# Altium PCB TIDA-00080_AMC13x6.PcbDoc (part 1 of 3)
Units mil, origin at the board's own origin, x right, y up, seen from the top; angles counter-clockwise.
Board outline 7283.46 x 2559.06 mil, 4 copper layers (Top Layer, MidLayer1, MidLayer2, Bottom Layer), stack 61.2 mil thick; 372 components, 160 nets, 901 pads, 256 vias.
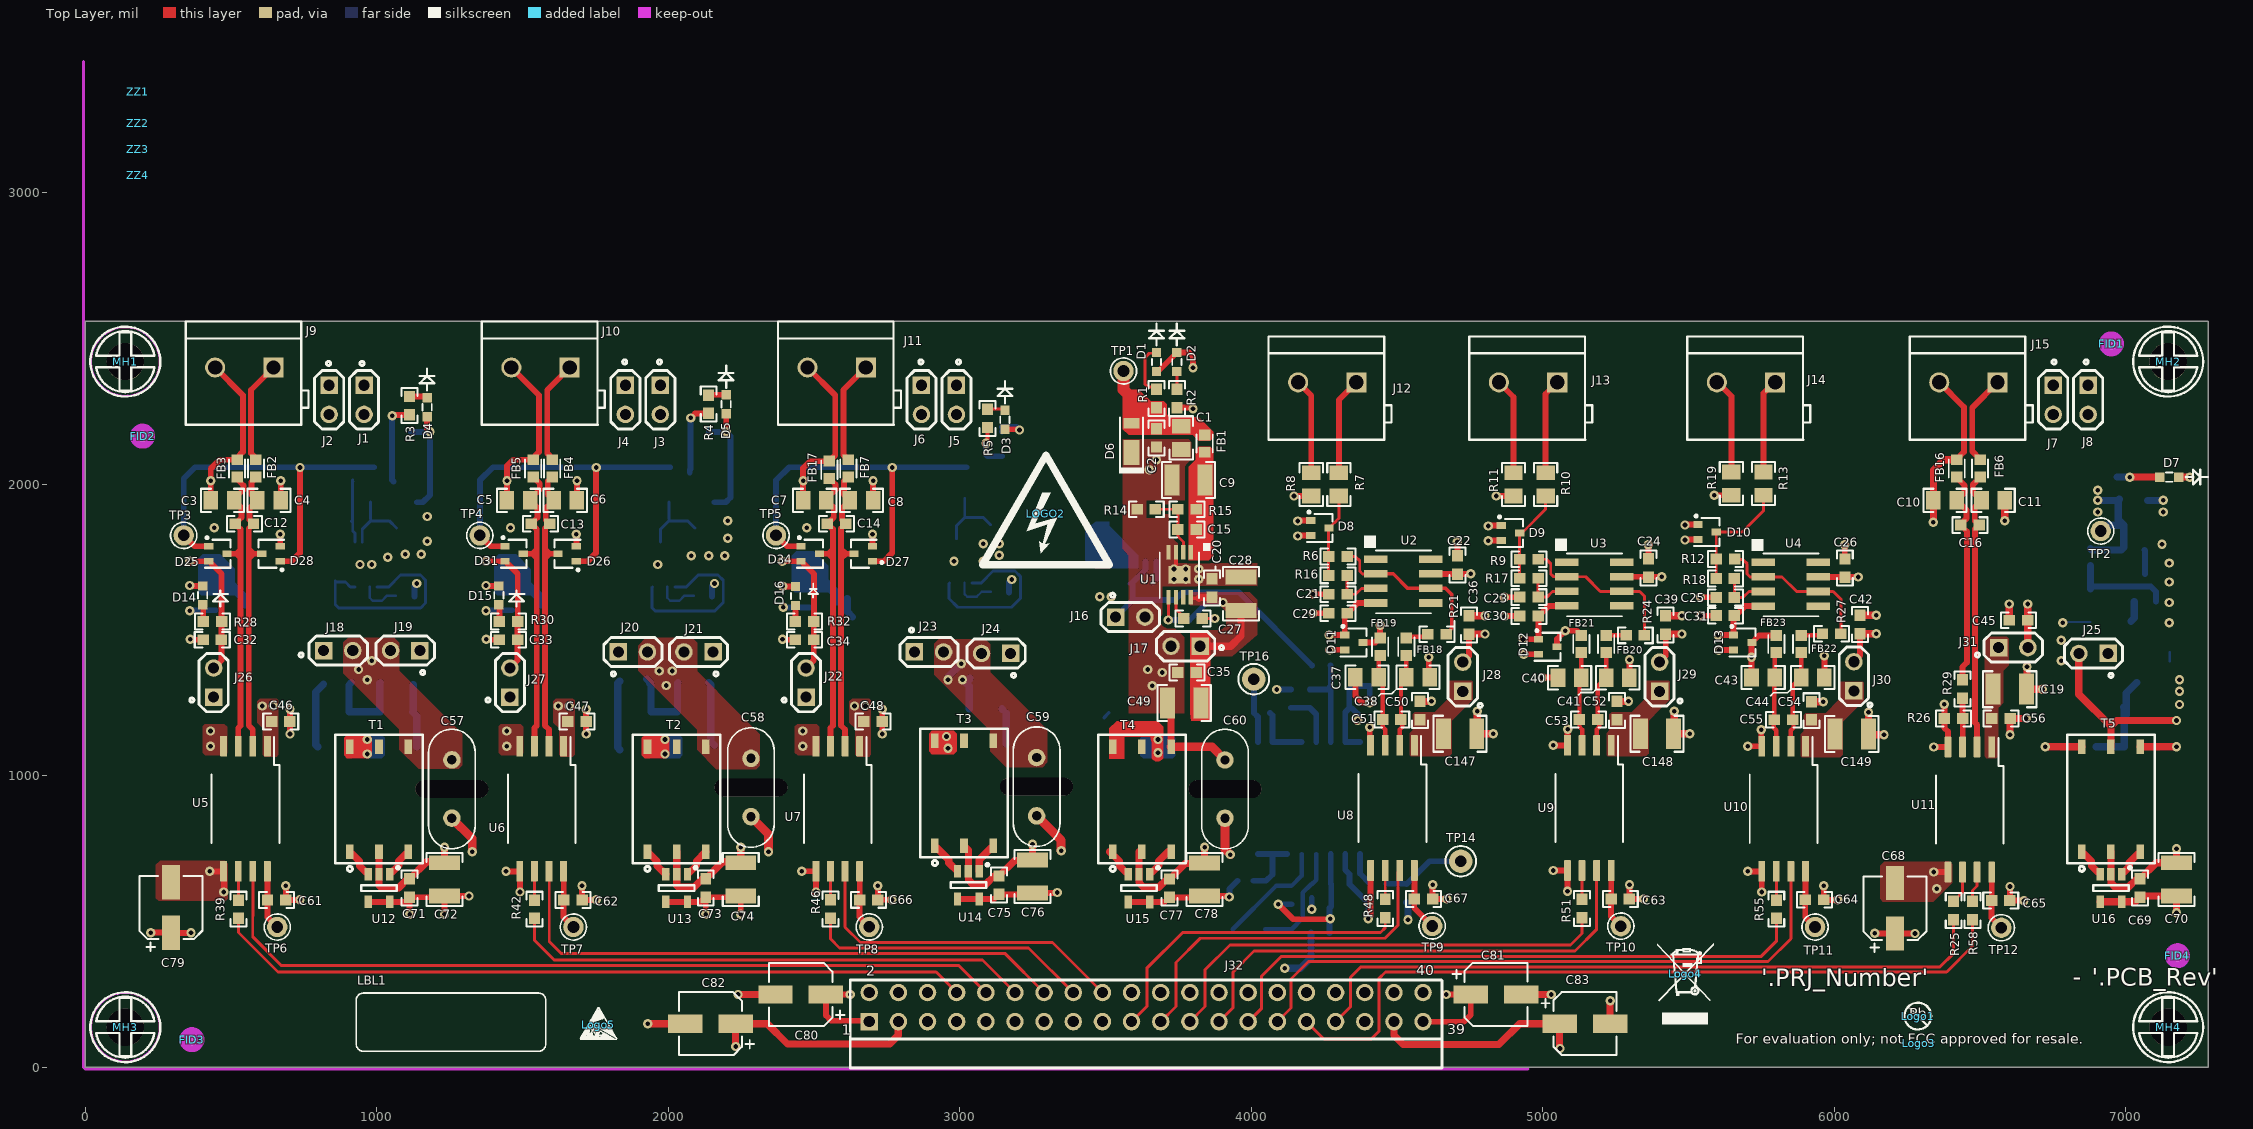
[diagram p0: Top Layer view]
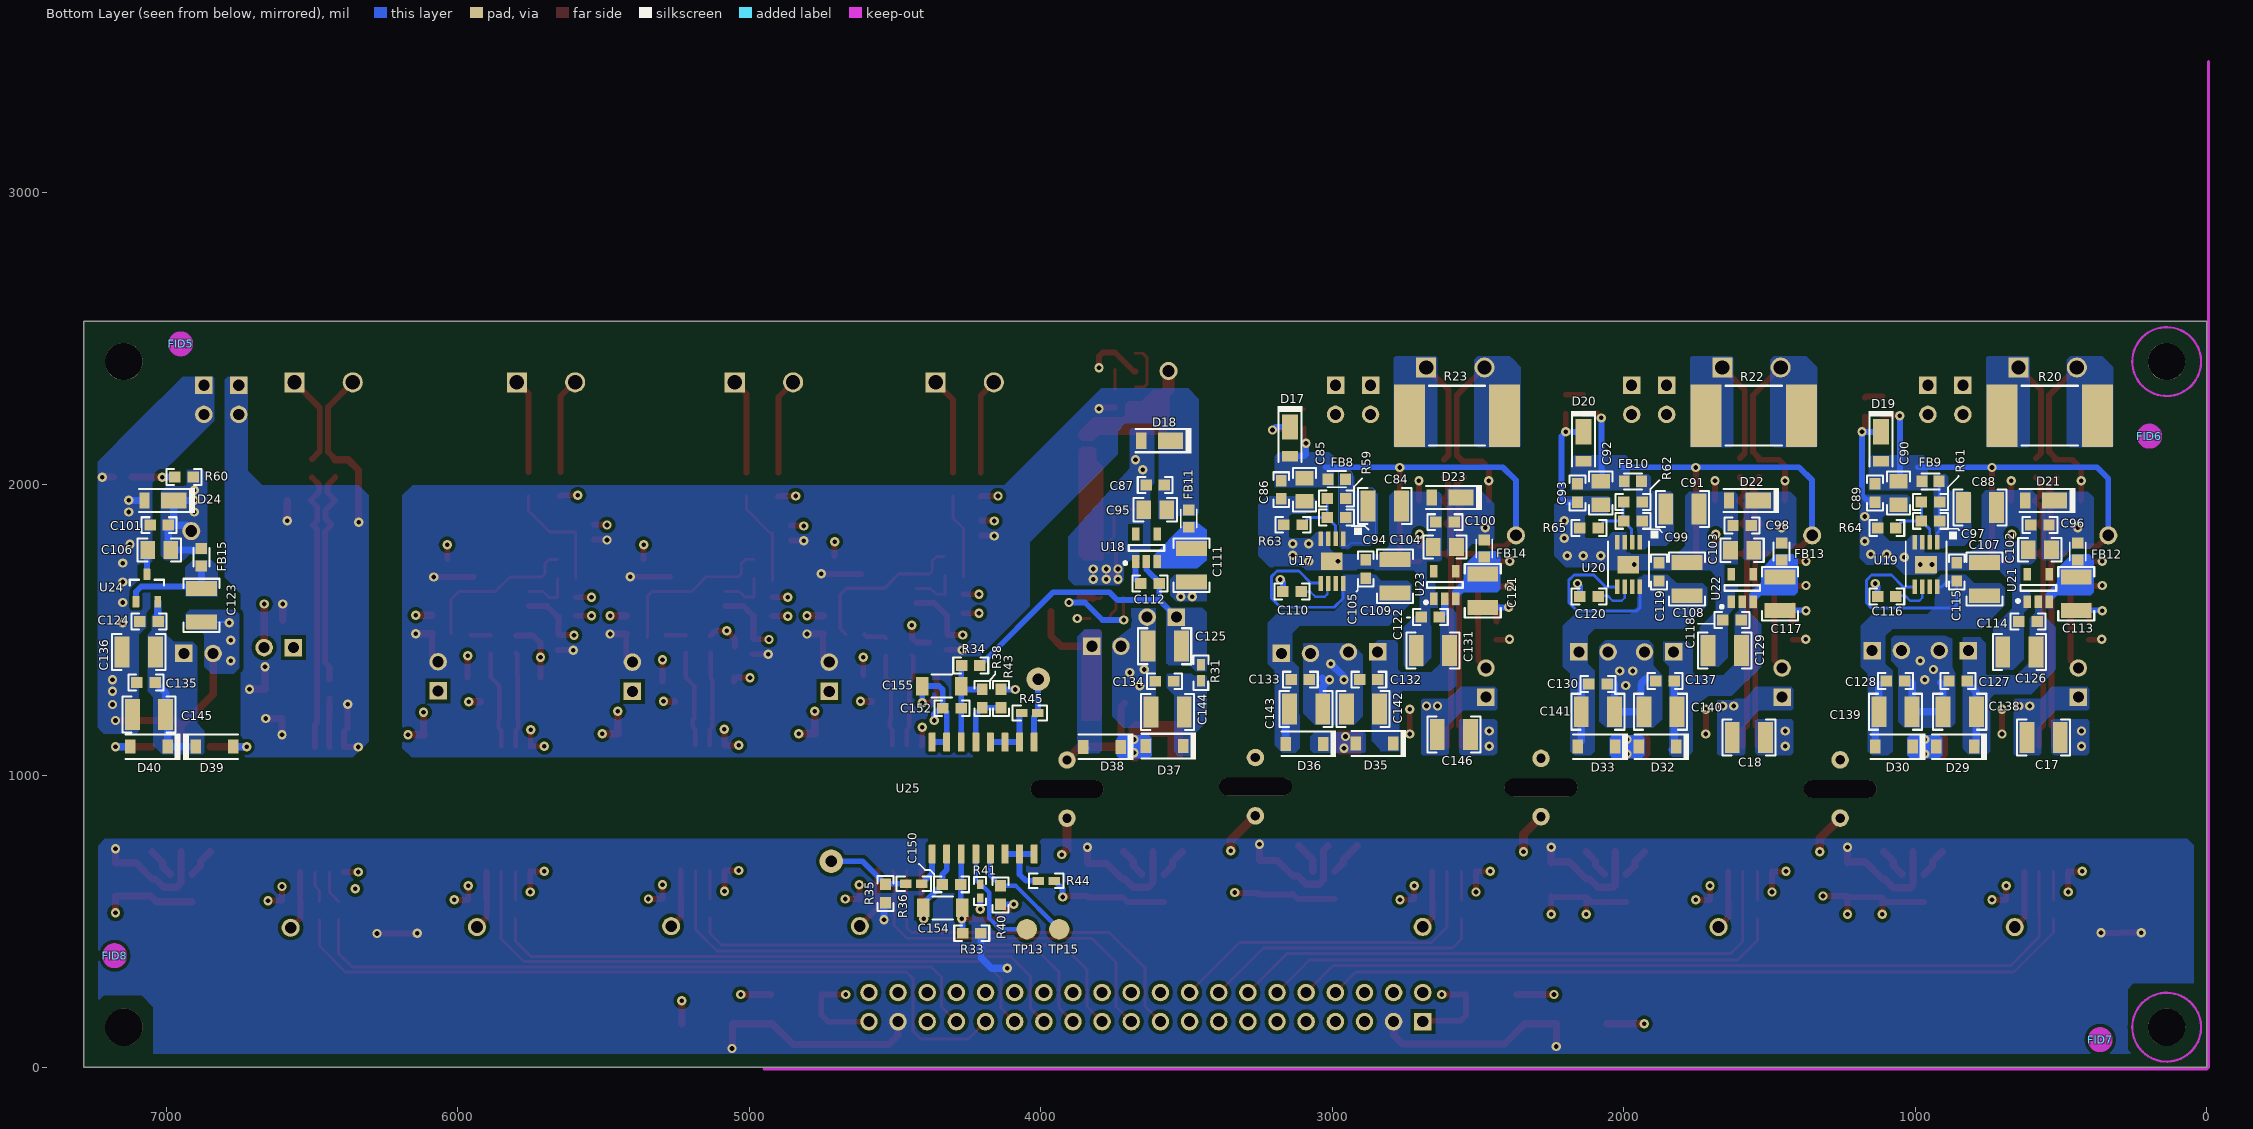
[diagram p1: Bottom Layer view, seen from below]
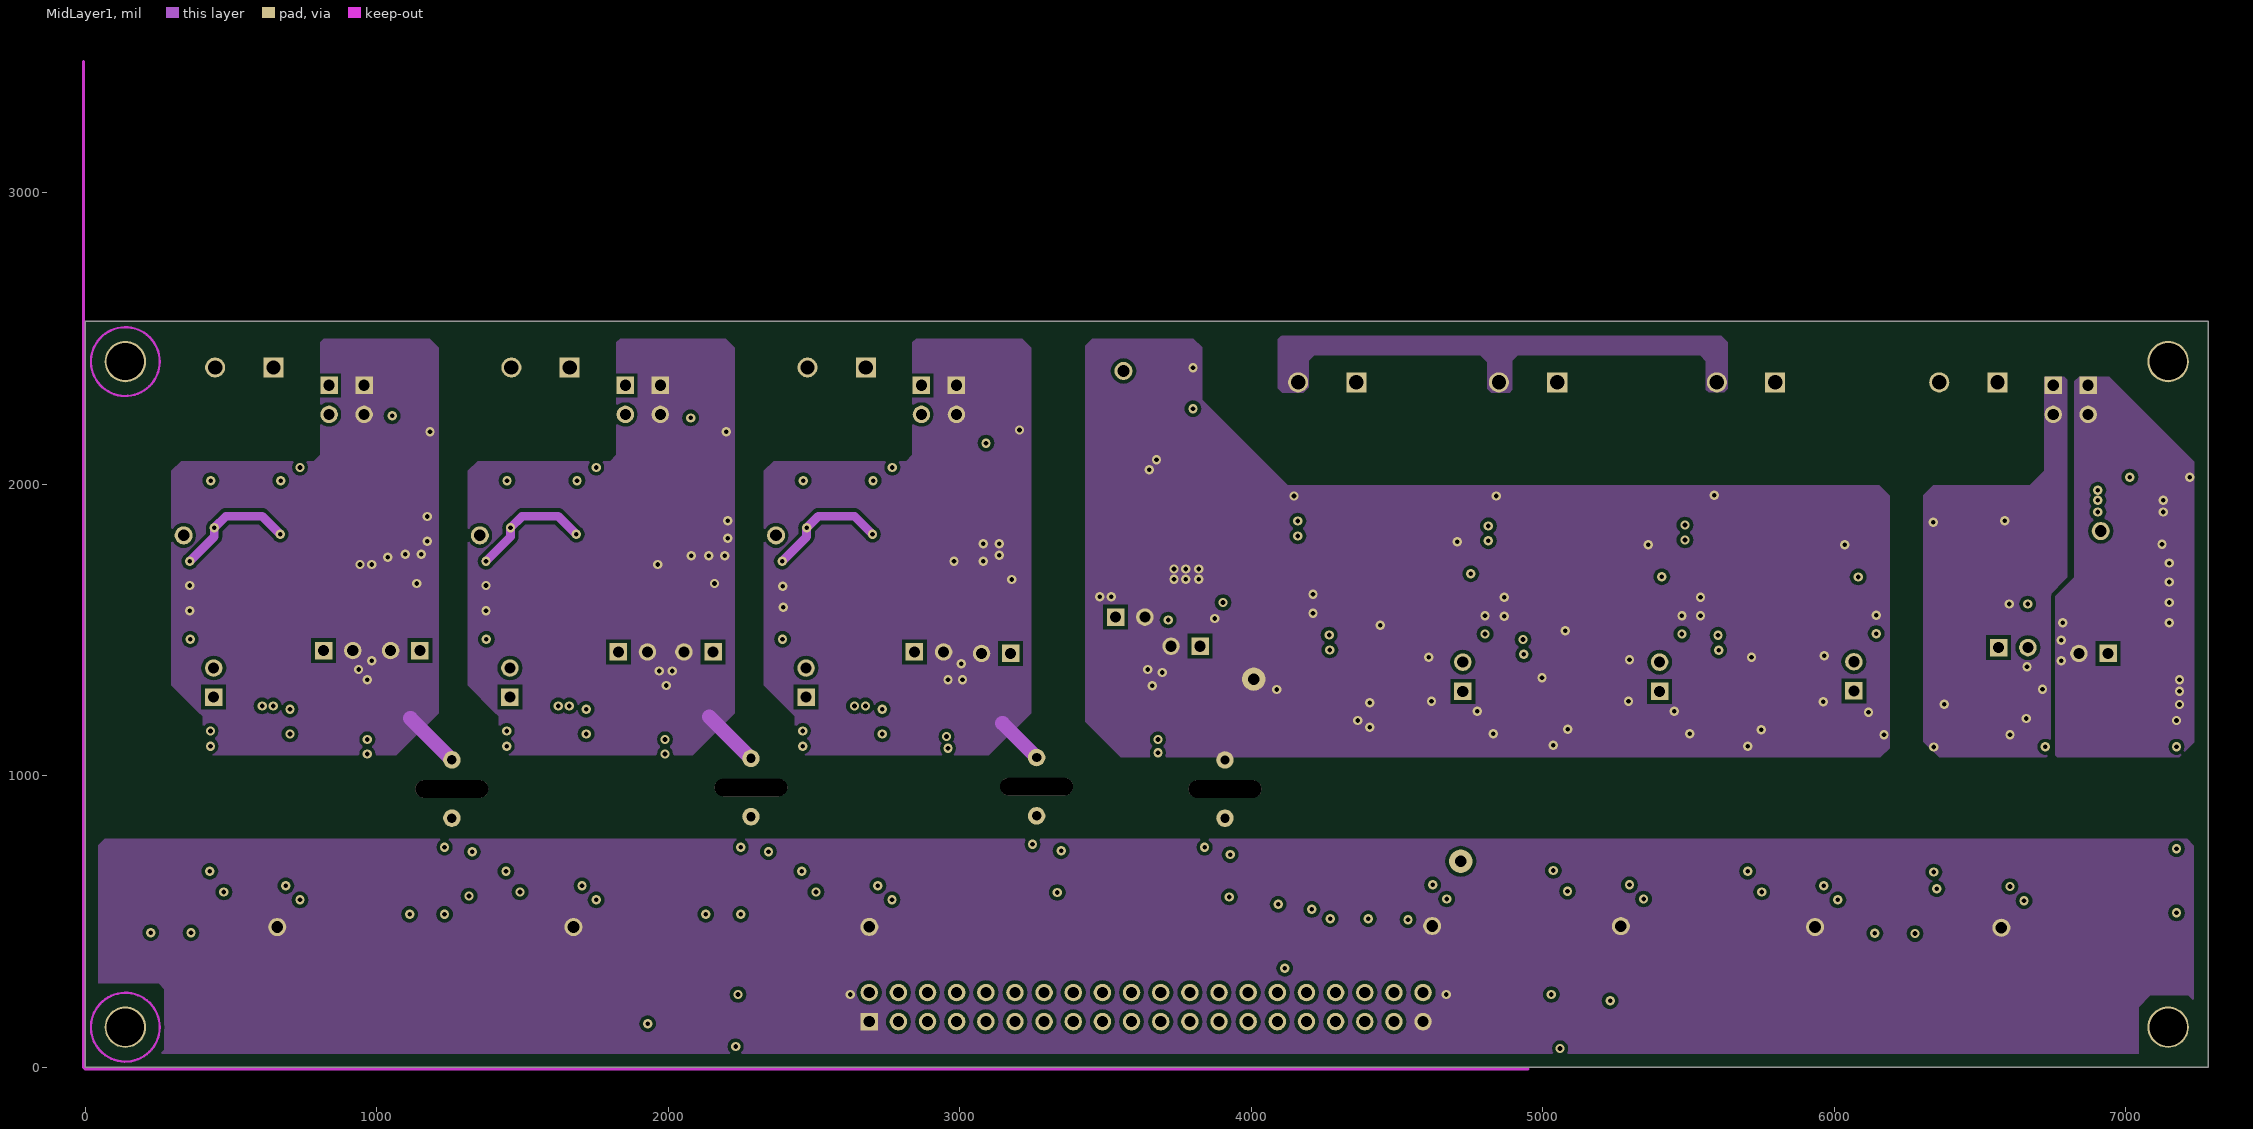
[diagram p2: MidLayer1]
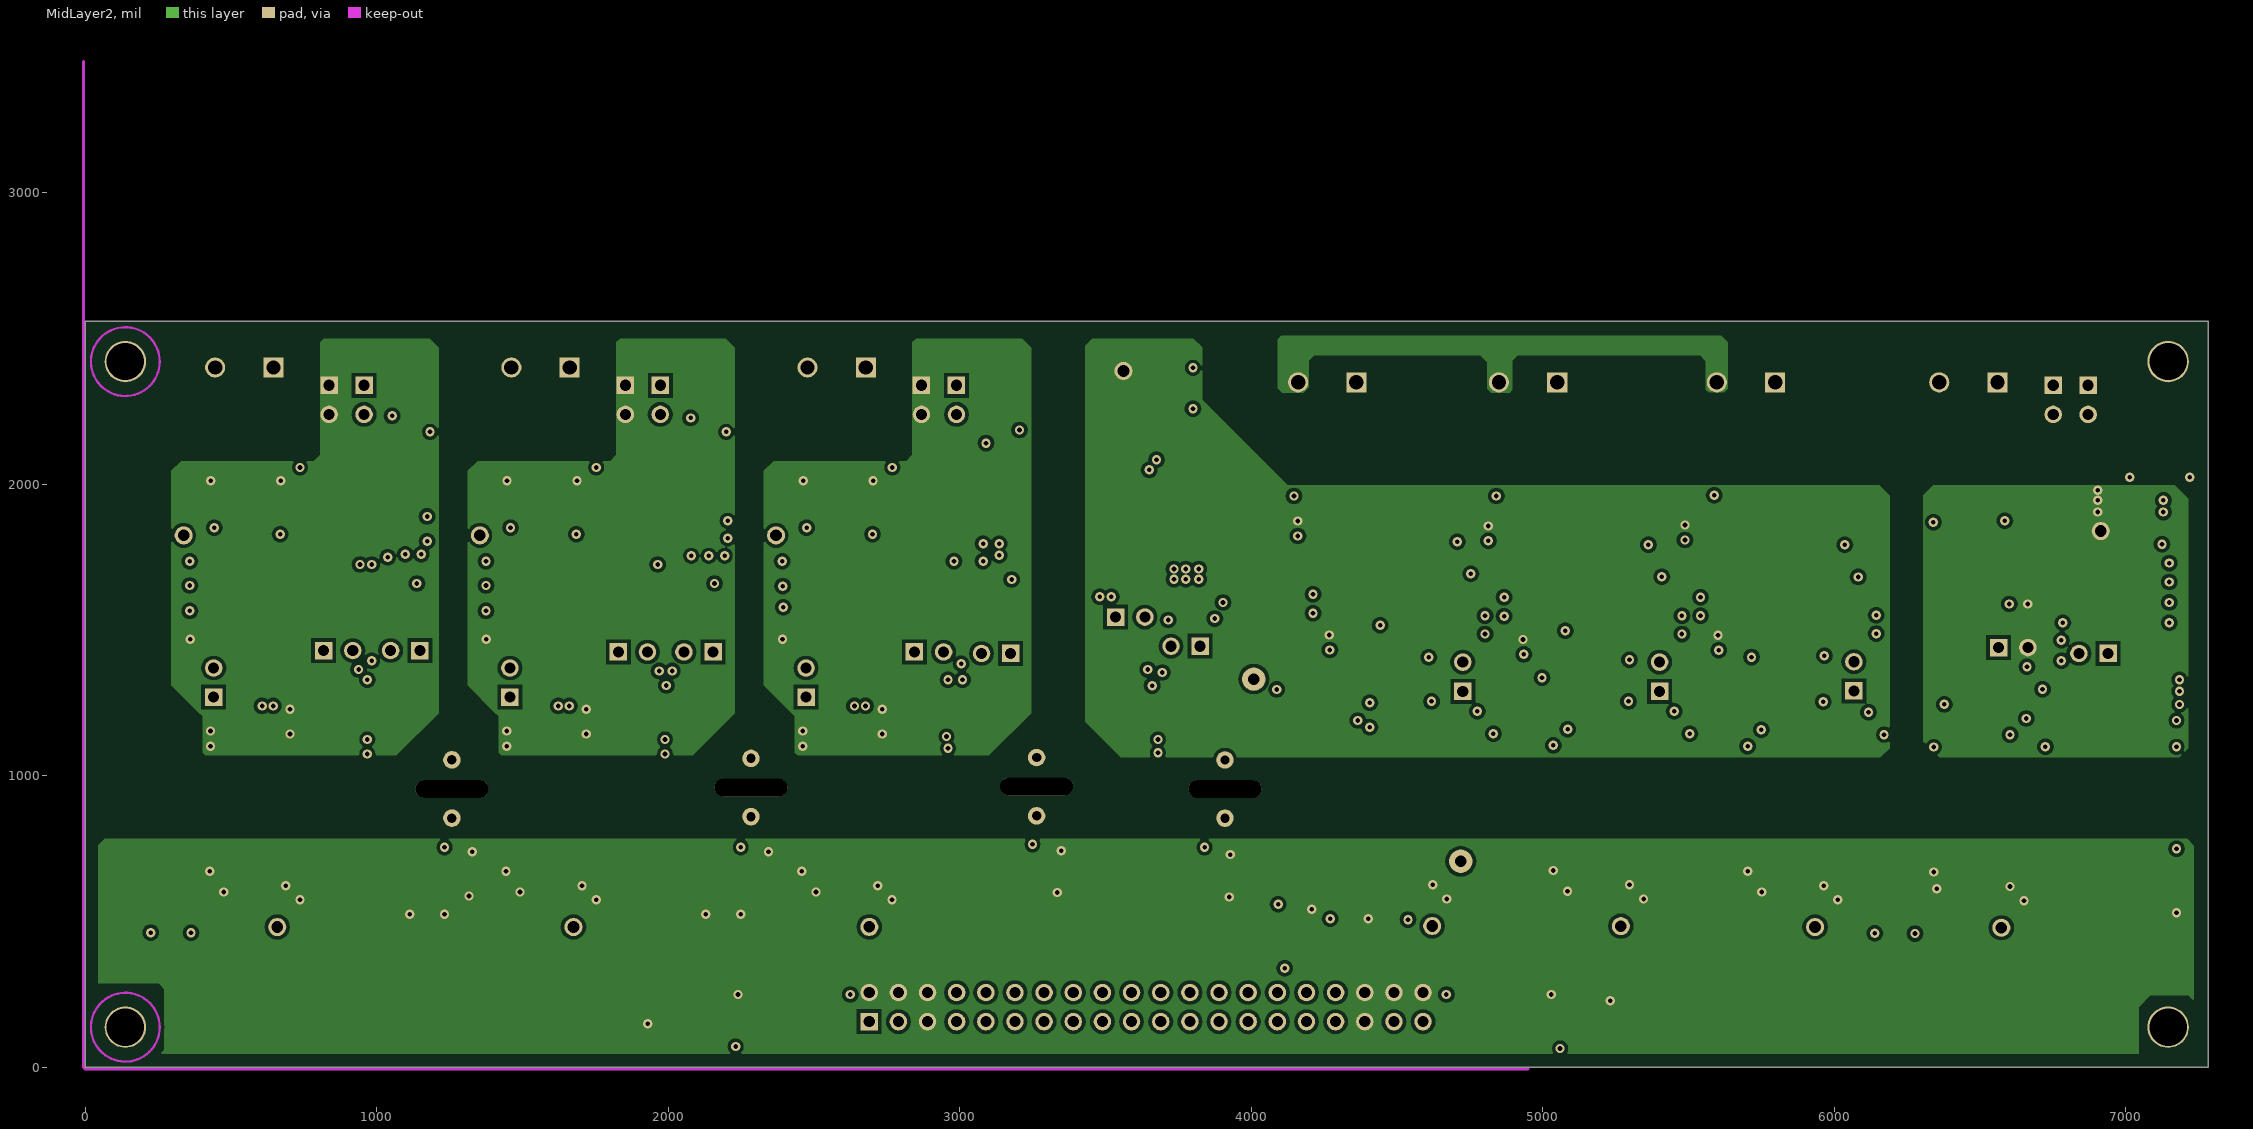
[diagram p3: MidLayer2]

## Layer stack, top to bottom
Top Solder: solder mask 0.4, Solder Resist, Dk 3.5
Top Layer: signal copper 2.8
Dielectric1: core 16.6, FR-4, Dk 4.8
MidLayer1: signal copper 2.8
Dielectric2: prepreg 16.8, FR-4, Dk 4.8
MidLayer2: signal copper 2.8
Dielectric3: core 16.6, FR-4, Dk 4.8
Bottom Layer: signal copper 2.8
Bottom Solder: solder mask 0.4, Solder Resist, Dk 3.5

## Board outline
0,0 7283.46,0 7283.46,2559.06 0,2559.06

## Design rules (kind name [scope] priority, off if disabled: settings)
AcuteAngle [All] p1 off: minimum=4.50000000000000E+0001 checktracksonly=FALSE
AssemblyTestPointUsage [All] p1 off: valid=2
AssemblyTestpoint [All] p1 off: testpointundercomponent=TRUE minsize=40 maxsize=100 preferedsize=60 minholesize=0 maxholesize=40 preferedholesize=32 testpointgrid=1 usegrid=TRUE gridtolerance=0.01 allowsidetop=TRUE allowsidebottom=TRUE
Clearance Clearance_POLY_POLY [InPoly vs InPoly] p1: gap=15 ignorepadtopadclearanceinfootprint=FALSE except(0: Arc-Hole Track-Hole SMDPad-Hole THPad-Hole Via-Hole Fill-Hole Poly-Hole Region-Hole Text-Hole)
Clearance Clearance_Poly [InPolygon] p2: gap=12 ignorepadtopadclearanceinfootprint=FALSE except(0: Arc-Hole Track-Hole SMDPad-Hole THPad-Hole Via-Hole Fill-Hole Poly-Hole Region-Hole Text-Hole)
Clearance [All] p3: gap=8 ignorepadtopadclearanceinfootprint=FALSE except(0: Arc-Hole Track-Hole SMDPad-Hole THPad-Hole Via-Hole Fill-Hole Poly-Hole Region-Hole Text-Hole)
ComponentClearance ComponentClearance_Logo [InComponentClass('Logo')] p1 off: gap=50 collisioncheckmode=3 verticalgap=10 showdistances=FALSE
ComponentClearance ComponentClearance_ScrewToNut [(HasFootprint('NY PMS 440 0025 PH')) vs (HasFootprint('Keystone_1902C'))] p2 off: gap=5 collisioncheckmode=3 verticalgap=10 showdistances=FALSE
ComponentClearance ComponentClearance_MountingHoles [InComponentClass('Mounting Holes')] p3 off: gap=250 collisioncheckmode=3 verticalgap=100000 showdistances=FALSE
ComponentClearance ComponentClearance_SmallPassives [HasFootprint('0201*') or HasFootprint('0402*') or HasFootprint('0508') or HasFootprint('0603*') or HasFootprint('0612') or HasFootprint('0805*') or HasFootprint('0815*') or HasFootprint('0830*') or HasFootprint('1206*') or HasFootprint('1210*') or HasFootprint('1808*') or HasFootprint('1812*') or HasFootprint('1825*') or HasFootprint('2010*') or HasFootprint('2220*') or HasFootprint('2225*') or HasFootprint('2512*') or HasFootprint('2728*') or HasFootprint('3518*') vs HasFootprint('0201*') or HasFootprint('0402*') or HasFootprint('0508') or HasFootprint('0603*') or HasFootprint('0612') or HasFootprint('0805*') or HasFootprint('0815*') or HasFootprint('0830*') or HasFootprint('1206*') or HasFootprint('1210*') or HasFootprint('1808*') or HasFootprint('1812*') or HasFootprint('1825*') or HasFootprint('2010*') or HasFootprint('2220*') or HasFootprint('2225*') or HasFootprint('2512*') or HasFootprint('2728*') or HasFootprint('3518*')] p4 off: gap=20 collisioncheckmode=3 verticalgap=10 showdistances=FALSE
ComponentClearance ComponentClearance_THtoSMT [IsThruComponent vs IsSMTComponent] p5 off: gap=100 collisioncheckmode=3 verticalgap=30 showdistances=FALSE
ComponentClearance ComponentClearance_THtoTH [IsThruComponent vs IsThruComponent] p6 off: gap=118.11 collisioncheckmode=3 verticalgap=30 showdistances=FALSE
ComponentClearance [All] p7 off: gap=40 collisioncheckmode=3 verticalgap=10 showdistances=FALSE
DiffPairsRouting DiffPair_RS232DiffPairsRouting [InDifferentialPair ('RS232')] p1: maxlimit=8 minlimit=8 mostfreqgap=8 toplayer_minwidth=15 toplayer_maxwidth=15 toplayer_prefwidth=15 midlayer1_minwidth=15 midlayer1_maxwidth=15 midlayer1_prefwidth=15 midlayer2_minwidth=15 midlayer2_maxwidth=15 midlayer2_prefwidth=15 bottomlayer_minwidth=15 bottomlayer_maxwidth=15 bottomlayer_prefwidth=15 maxuncoupledlength=500
DiffPairsRouting [All] p2: maxlimit=100 minlimit=10 mostfreqgap=10 toplayer_minwidth=15 toplayer_maxwidth=15 toplayer_prefwidth=15 midlayer1_minwidth=15 midlayer1_maxwidth=15 midlayer1_prefwidth=15 midlayer2_minwidth=15 midlayer2_maxwidth=15 midlayer2_prefwidth=15 bottomlayer_minwidth=15 bottomlayer_maxwidth=15 bottomlayer_prefwidth=15 maxuncoupledlength=1000
FabricationTestPointUsage TestPointUsage [All] p1 off: valid=2 allowmultiple=FALSE
FabricationTestpoint Testpoint [All] p1 off: side=3 testpointundercomponent=TRUE minsize=40 maxsize=100 preferedsize=60 minholesize=0 maxholesize=40 preferedholesize=32 testpointgrid=1 allowsidetop=TRUE allowsidebottom=TRUE usegrid=TRUE gridtolerance=0.01
FanoutControl Fanout_LCC [IsLCC] p1 off: bgadir=Out bgaviamode=Centered fanoutstyle=Auto fanoutdirection=Alternating viagrid=1 // Fanout_LCC (Default Rule)
FanoutControl Fanout_BGA [IsBGA] p2 off: bgadir=Out bgaviamode=Centered fanoutstyle=Auto fanoutdirection=Alternating viagrid=1 // Fanout_BGA (Default Rule)
FanoutControl Fanout_SOIC [IsSOIC] p3 off: bgadir=Out bgaviamode=Centered fanoutstyle=Auto fanoutdirection=Alternating viagrid=1 // Fanout_SOIC (Default Rule)
FanoutControl Fanout_Default [All] p4 off: bgadir=Out bgaviamode=Centered fanoutstyle=Auto fanoutdirection=Alternating viagrid=1 // Fanout_Default (Default Rule)
FanoutControl Fanout_Small [(CompPinCount < 5)] p5 off: bgadir=Out bgaviamode=Centered fanoutstyle=Auto fanoutdirection=OutThenIn viagrid=1 // Fanout_Small (Default Rule)
Height [All] p1 off: minheight=0 maxheight=1000 prefheight=500
HoleSize [All] p1 off: absolutevalues=TRUE maxlimit=251 minlimit=8 maxpercent=80.000 minpercent=20.000
HoleToHoleClearance [All] p1 off: gap=10 allowstackedmicrovias=TRUE
LayerPairs [All] p1 off: enforce=TRUE
MatchedLengths DiffPair_RS232MatchedLengths [InDifferentialPair ('RS232')] p1: tolerance=1000 checknetsindiffpair=TRUE checkdiffpairvsdiffpair=FALSE checkxsignals=FALSE checkothers=FALSE
MinimumAnnularRing MinimumAnnularRing_ThermalPadVias [IsVia and InAnyComponent] p1 off: minimumring=5.91
MinimumAnnularRing [All] p2 off: minimumring=8
MinimumSolderMaskSliver MinimumSolderMaskSliver_Logo [InComponentClass('Logo') vs InComponentClass('Logo')] p1 off: minsoldermaskwidth=0.7
MinimumSolderMaskSliver [All] p2 off: minsoldermaskwidth=3.94
NetAntennae [All] p1 off: netantennaetolerance=0
PasteMaskExpansion [All] p1 off: expansion=0
PlaneClearance [All] p1: clearance=15
PlaneConnect [All] p1: planeconnectstyle=Direct reliefexpansion=10 reliefentries=4 reliefconductorwidth=10 reliefairgap=10
PolygonConnect [All] p1: connectstyle=Direct reliefconductorwidth=10 reliefentries=4 polygonreliefangle="90 Angle" airgapwidth=10
RoutingCorners [All] p1 off: cornerstyle=45-Degree minsetback=100 maxsetback=100
RoutingLayers [All] p1 off: top layer_v5=TRUE mid layer 1_v5=TRUE mid layer 2_v5=TRUE bottom layer_v5=TRUE
RoutingPriority [All] p1 off: routingpriority=0
RoutingTopology [All] p1 off: topology=Shortest
RoutingVias ThermalPadVias [IsVia and InAnyComponent] p1: holewidth=16 width=32 viastyle="Through Hole" minholewidth=16 minwidth=32 maxholewidth=16 maxwidth=32
RoutingVias [All] p2: holewidth=16 width=32 viastyle="Through Hole" minholewidth=16 minwidth=32 maxholewidth=16 maxwidth=32
SMDToCorner [All] p1 off: distance=30000
SilkToSilkClearance [All] p1 off: silktosilkclearance=5
SilkToSolderMaskClearance SilkscreenOverComponentPads [IsPad] p1 off: minsilkscreentomaskgap=5 clearancetoexposedcopper=TRUE
SolderMaskExpansion [All] p1 off: expansion=1.97
Width DiffPair_RS232Width [InDifferentialPair('RS232')] p1: maxlimit=10 minlimit=10 preferedwidth=10
Width [All] p2: maxlimit=100 minlimit=8 preferedwidth=25 checkconnectedcopper=TRUE
4 further rules are at their usual default settings.

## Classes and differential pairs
component class "Pg6-Power supply 3": C1 C2 C9 C15 C20 C27 C28 C35 C49 C60 C77 C78 C87 C95 C111 C112 C125 C134 C144 C150 C152 C154 C155 D1 D2 D6 D18 D37 D38 FB1 FB11 J16 J17 R1 R2 R14 R15 R31 R33 R34 R35 R36 R38 R40 R41 R43 R44 R45 T4 TP1 TP13 TP14 TP15 TP16 U1 U15 U18 U25
component class "Pg3-Voltage signal condtioning": C21 C22 C23 C24 C25 C26 C29 C30 C31 C36 C37 C38 C39 C40 C41 C42 C43 C44 C50 C51 C52 C53 C54 C55 C63 C64 C67 C147 C148 C149 D8 D9 D10 D11 D12 D13 FB18 FB19 FB20 FB21 FB22 FB23 J12 J13 J14 J28 J29 J30 R6 R7 R8 R9 R10 R11 R12 R13 R16 R17 R18 R19 R21 R24 R27 R48 R51 R55 TP9 TP10 TP11 U2 U3 U4 U8 U9 U10
component class "Pg5-Power supply 2": C59 C68 C69 C70 C75 C76 C84 C85 C86 C94 C100 C101 C104 C105 C106 C109 C110 C121 C122 C123 C124 C131 C132 C133 C135 C136 C142 C143 C145 D3 D7 D16 D17 D23 D24 D35 D36 D39 D40 FB8 FB14 FB15 J5 J8 J23 J24 J25 R5 R32 R59 R60 R63 T3 T5 TP2 TP5 U14 U16 U17 U23 U24
component class "Pg4-Power supply 1": C57 C58 C71 C72 C73 C74 C79 C88 C89 C90 C91 C92 C93 C96 C97 C98 C99 C102 C103 C107 C108 C113 C114 C115 C116 C117 C118 C119 C120 C126 C127 C128 C129 C130 C137 C138 C139 C140 C141 D4 D5 D14 D15 D19 D20 D21 D22 D29 D30 D32 D33 FB9 FB10 FB12 FB13 J1 J3 J18 J19 J20 J21 R3 R4 R28 R30 R61 R62 R64 R65 T1 T2 TP3 TP4 U12 U13 U19 U20 U21 U22
component class Label: LBL1
component class AssemblyNote: ZZ1 ZZ2 ZZ3 ZZ4
component class FiducialMark: FID1 FID2 FID3 FID4 FID5 FID6 FID7 FID8
component class Pg7-Hardware: FID1 FID2 FID3 FID4 FID5 FID6 FID7 FID8 LBL1 Logo1 LOGO2 Logo3 Logo4 Logo5 MH1 MH2 MH3 MH4 ZZ1 ZZ2 ZZ3 ZZ4
component class "Mounting Holes": MH1 MH2 MH3 MH4
component class "Pg2-Current Sense": C3 C4 C5 C6 C7 C8 C10 C11 C12 C13 C14 C16 C17 C18 C19 C32 C33 C34 C45 C46 C47 C48 C56 C61 C62 C65 C66 C80 C81 C82 C83 C146 D25 D26 D27 D28 D31 D34 FB2 FB3 FB4 FB5 FB6 FB7 FB16 FB17 J2 J4 J6 J7 J9 J10 J11 J15 J22 J26 J27 J31 J32 R20 R22 R23 R25 R26 R29 R39 R42 R46 R58 TP6 TP7 TP8 TP12 U5 U6 U7 U11

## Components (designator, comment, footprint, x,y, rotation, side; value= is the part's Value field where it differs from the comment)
C1 "" 0805_HV 3760.2,2159.72 r90 top value=4.7uF
C2 "" 0603 3675.2,2159.72 r270 top value=0.1uF
C3 "GRM21A5C2E470JW01D" 0805_HV 471,1945 r0 top value=47pF
C4 "GRM21A5C2E470JW01D" 0805_HV 631,1945 r0 top value=47pF
C5 "GRM21A5C2E470JW01D" 0805_HV 1487,1945 r0 top value=47pF
C6 "GRM21A5C2E470JW01D" 0805_HV 1647,1945 r0 top value=47pF
C7 "GRM21A5C2E470JW01D" 0805_HV 2502.99,1945 r0 top value=47pF
C8 "GRM21A5C2E470JW01D" 0805_HV 2662.99,1945 r0 top value=47pF
C9 "" 1210 3785.2,2014.72 r0 top value=10uF
C10 "GRM21A5C2E470JW01D" 0805_HV 6380.45,1945 r0 top value=47pF
C11 "GRM21A5C2E470JW01D" 0805_HV 6545.45,1945 r0 top value=47pF
C12 "06031C152KAT2A" 0603 546,1865 r180 top value=1500pF
C13 "06031C152KAT2A" 0603 1562,1865 r180 top value=1500pF
C14 "06031C152KAT2A" 0603 2577.99,1865 r180 top value=1500pF
C15 "" 0603 3780.2,1844.72 r0 top value=0.01uF
C16 "06031C152KAT2A" 0603 6465.45,1860 r180 top value=1500pF
C17 "" 1210 560.09,1132 r0 bottom value=10uF
C18 "" 1210 1571,1132 r0 bottom value=10uF
C19 "" 1210 6602.37,1297.22 r180 top value=10uF
C20 "" 0603 3865.2,1644.72 r90 top value=0.1uF
C21 "" 0603 4297.38,1623.01 r180 top value=4700pF
C22 "" 0603 4707.38,1723.01 r270 top value=0.1uF
C23 "" 0603 4952.69,1613.01 r180 top value=4700pF
C24 "" 0603 5362.69,1713.01 r270 top value=0.1uF
C25 "" 0603 5626.5,1612.5 r180 top value=4700pF
C26 "" 0603 6036.5,1712.5 r270 top value=0.1uF
C27 "" 0603 3800.2,1539.72 r180 top value=0.01uF
C28 "" 1210 3965.2,1624.72 r270 top value=10uF
C29 "" 0603 4297.38,1558.01 r0 top value=0.1uF
C30 "" 0603 4952.69,1548.01 r0 top value=0.1uF
C31 "" 0603 5626.5,1549.5 r0 top value=0.1uF
C32 "" 0603 436,1467 r180 top value=0.1uF
C33 "" 0603 1452,1467 r180 top value=0.1uF
C34 "" 0603 2467.99,1467 r180 top value=0.1uF
C35 "" 0603 3780.2,1354.72 r0 top value=0.1uF
C36 "" 0603 4746.89,1518.01 r90 top value=0.1uF
C37 "GRM21A5C2E470JW01D" 0805_HV 4397.38,1338.01 r0 top value=47pF
C38 "GRM21A5C2E470JW01D" 0805_HV 4572.38,1338.01 r180 top value=47pF
C39 "" 0603 5421.69,1517.5 r90 top value=0.1uF
C40 "GRM21A5C2E470JW01D" 0805_HV 5092.69,1337.01 r0 top value=47pF
C41 "GRM21A5C2E470JW01D" 0805_HV 5257.69,1337.01 r180 top value=47pF
C42 "" 0603 6088.5,1519.5 r90 top value=0.1uF
C43 "GRM21A5C2E470JW01D" 0805_HV 5756.5,1337.5 r0 top value=47pF
C44 "GRM21A5C2E470JW01D" 0805_HV 5926.5,1337.5 r180 top value=47pF
C45 "" 0603 6632.45,1534 r180 top value=0.1uF
C46 "" 0603 671,1186 r0 top value=0.1uF
C47 "" 0603 1687,1186 r0 top value=0.1uF
C48 "" 0603 2702.99,1186 r0 top value=0.1uF
C49 "" 1210 3770.2,1249.72 r0 top value=10uF
C50 "" 0603 4579.38,1224.01 r90 top value=0.1uF
C51 "06031C152KAT2A" 0603 4482.38,1193.01 r180 top value=1500pF
C52 "" 0603 5254.69,1224.01 r90 top value=0.1uF
C53 "06031C152KAT2A" 0603 5157.69,1193.01 r180 top value=1500pF
C54 "" 0603 5922.5,1223.5 r90 top value=0.1uF
C55 "06031C152KAT2A" 0603 5826.5,1192.5 r180 top value=1500pF
C56 "" 0603 6571.94,1196.8 r0 top value=0.1uF
C57 "" CAP_200mil#1 1258,955 r90 top value=1000pF
C58 "" CAP_200mil#1 2284,960 r90 top value=1000pF
C59 "" CAP_200mil#1 3264,963 r90 top value=1000pF
C60 "" CAP_200mil#2 3910.2,954.72 r90 top value=1000pF
C61 "" 0603 657,574.5 r180 top value=0.1uF
C62 "" 0603 1673,574.5 r180 top value=0.1uF
C63 "" 0603 5266.19,577.51 r180 top value=0.1uF
C64 "" 0603 5933,575 r180 top value=0.1uF
C65 "" 0603 6571.45,572 r180 top value=0.1uF
C66 "" 0603 2687.99,574.87 r180 top value=0.1uF
C67 "" 0603 4590.89,577.51 r180 top value=0.1uF
C68 "UUD1E220MCL1GS" SM_RADIAL_5MM 6208.45,546 r90 top value=22uF
C69 "" 0603 7049.45,615 r90 top value=0.1uF
C70 "" 1210 7174.45,645 r90 top value=10uF
C71 "" 0603 1113,615 r90 top value=0.1uF
C72 "" 1210 1233,645 r90 top value=10uF
C73 "" 0603 2129,615 r90 top value=0.1uF
C74 "" 1210 2249,645 r90 top value=10uF
C75 "" 0603 3135,625 r90 top value=0.1uF
C76 "" 1210 3250,655 r90 top value=10uF
C77 "" 0603 3720.2,614.72 r90 top value=0.1uF
C78 "" 1210 3840.2,644.72 r90 top value=10uF
C79 "UUD1E220MCL1GS" SM_RADIAL_5MM 294.39,548.12 r90 top value=22uF
C80 "UUD1E220MCL1GS" SM_RADIAL_5MM 2454.72,250 r180 top value=22uF
C81 "UUD1E220MCL1GS" SM_RADIAL_5MM 4839.72,250 r0 top value=22uF
C82 "UUD1E220MCL1GS" SM_RADIAL_5MM 2144.72,150 r180 top value=22uF
C83 "UUD1E220MCL1GS" SM_RADIAL_5MM 5144.72,150 r0 top value=22uF
C84 "" 1210 2820.4,1926 r0 bottom value=10uF
C85 "" 0805_HV 3095.4,1981.6 r90 bottom value=4.7uF
C86 "" 0603 3175.4,1981.6 r270 bottom value=0.1uF
C87 "" 0603 3607.6,1997.48 r0 bottom value=0.1uF
C88 "" 1210 778,1920 r0 bottom value=10uF
C89 "" 0603 1138,1970 r270 bottom value=0.1uF
C90 "" 0805_HV 1058,1970 r90 bottom value=4.7uF
C91 "" 1210 1799,1916 r0 bottom value=10uF
C92 "" 0805_HV 2079,1970 r90 bottom value=4.7uF
C93 "" 0603 2159,1970 r270 bottom value=0.1uF
C94 "" 0603 2985.4,1886.6 r180 bottom value=0.01uF
C95 "" 0805_HV 3607.6,1912.48 r180 bottom value=4.7uF
C96 "" 0603 573,1860.32 r0 bottom value=0.1uF
C97 "" 0603 948,1875 r180 bottom value=0.01uF
C98 "" 0603 1594,1859.5 r0 bottom value=0.1uF
C99 "" 0603 1969,1875 r180 bottom value=0.01uF
C100 "" 0603 2614,1870.27 r0 bottom value=0.1uF
C101 "" 0603 7024.45,1860 r0 bottom value=0.1uF
C102 "" 0805_HV 573,1775.32 r180 bottom value=4.7uF
C103 "" 0805_HV 1594,1774.5 r180 bottom value=4.7uF
C104 "" 0805_HV 2614,1785.27 r180 bottom value=4.7uF
C105 "" 0603 2885.4,1710 r90 bottom value=0.1uF
C106 "" 0805_HV 7024.45,1775 r180 bottom value=4.7uF
C107 "" 1210 763,1675 r270 bottom value=10uF
C108 "" 1210 1784,1675 r270 bottom value=10uF
C109 "" 1210 2785.4,1685 r270 bottom value=10uF
C110 "" 0603 3138.2,1631.9 r180 bottom value=0.01uF
C111 "" 1210 3482.6,1722.48 r90 bottom value=10uF
C112 "" 0603 3625.2,1659.72 r0 bottom value=0.1uF
C113 "" 1210 448,1625 r90 bottom value=10uF
C114 "" 0603 613,1530 r0 bottom value=0.1uF
C115 "" 0603 858,1700 r90 bottom value=0.1uF
C116 "" 0603 1098,1615 r180 bottom value=0.01uF
C117 "" 1210 1464,1625 r90 bottom value=10uF
C118 "" 0603 1629,1535 r0 bottom value=0.1uF
C119 "" 0603 1879,1700 r90 bottom value=0.1uF
C120 "" 0603 2119,1615 r180 bottom value=0.01uF
C121 "" 1210 2484,1635.27 r90 bottom value=10uF
C122 "" 0603 2664,1545.27 r0 bottom value=0.1uF
C123 "" 1210 6879.45,1585 r90 bottom value=10uF
C124 "" 0603 7059.45,1530 r0 bottom value=0.1uF
C125 "" 1210 3575.2,1444.72 r180 bottom value=10uF
C126 "" 1210 643,1425 r180 bottom value=10uF
C127 "" 0603 853,1325 r0 bottom value=0.1uF
C128 "" 0603 1068,1325 r0 bottom value=0.1uF
C129 "" 1210 1654,1430 r180 bottom value=10uF
C130 "" 0603 2089,1315 r0 bottom value=0.1uF
C131 "" 1210 2655,1430 r180 bottom value=10uF
C132 "" 0603 2875,1330 r0 bottom value=0.1uF
C133 "" 0603 3110,1330 r0 bottom value=0.1uF
C134 "" 0603 3575.2,1324.72 r0 bottom value=0.1uF
C135 "" 0603 7069.45,1320 r0 bottom value=0.1uF
C136 "" 1210 7094.45,1425 r180 bottom value=10uF
C137 "" 0603 1859,1325 r0 bottom value=0.1uF
C138 "" 1210 848,1220 r0 bottom value=10uF
C139 "" 1210 1068,1220 r0 bottom value=10uF
C140 "" 1210 1874,1220 r0 bottom value=10uF
C141 "" 1210 2089,1220 r0 bottom value=10uF
C142 "" 1210 2895,1230 r0 bottom value=10uF
C143 "" 1210 3090,1230 r0 bottom value=10uF
C144 "" 1210 3565.2,1219.72 r0 bottom value=10uF
C145 "" 1210 7059.45,1210 r0 bottom value=10uF
C146 "" 1210 2583,1142 r0 bottom value=10uF
C147 "" 1210 4716.9,1144.52 r180 top value=10uF
C148 "" 1210 5392.2,1144.52 r180 top value=10uF
C149 "" 1210 6060.5,1143.5 r180 top value=10uF
C150 "C0603C104K5RACTU" 0603 4306,628 r180 bottom value=0.1uF
C152 "C0603C104K5RACTU" 0603 4305,1232 r180 bottom value=0.1uF
C154 "GRM31CR61H106KA12L" 1206_180 4336,547 r0 bottom value=10uF
C155 "GRM31CR61H106KA12L" 1206_180 4340,1308 r180 bottom value=10uF
D1 "" LED0603AA 3675.2,2419.72 r270 top value=Green
D2 "" LED0603AA 3745.2,2419.72 r270 top value=Green
D3 "" LED0603AA 3155.4,2221.6 r270 top value=Green
D4 "" LED0603AA 1173,2265 r270 top value=Green
D5 "" LED0603AA 2199,2275 r270 top value=Green
D6 "" powerDI123 3590.2,2159.72 r90 top value=6.2V
D7 "" LED0603AA 7149.45,2025 r180 top value=Green
D8 "DESD1P0RFW-7" SOT-323 4236,1850 r0 top value=DNP
D9 "DESD1P0RFW-7" SOT-323 4889.7,1833.39 r0 top value=DNP
D10 "DESD1P0RFW-7" SOT-323 5564.02,1836.39 r0 top value=DNP
D11 "" SOT-323 4352.38,1458.01 r0 top value=DESD1P0RFW-7
D12 "" SOT-323 5017.69,1443.01 r0 top value=DESD1P0RFW-7
D13 "" SOT-323 5686.5,1457.5 r0 top value=DESD1P0RFW-7
D14 "" LED0603AA 403,1619 r270 top value=Green
D15 "" LED0603AA 1419,1619 r270 top value=Green
D16 "" LED0603AA 2437,1616.99 r270 top value=Green
D17 "" powerDI123 3145.4,2146.6 r270 bottom value=6.2V
D18 "" powerDI123 3605.2,2149.72 r0 bottom value=6.2V
D19 "" powerDI123 1118,2130 r270 bottom value=6.2V
D20 "" powerDI123 2139,2130 r270 bottom value=6.2V
D21 "" powerDI123 573,1945 r0 bottom value=6.2V
D22 "" powerDI123 1589,1945 r0 bottom value=6.2V
D23 "" powerDI123 2609,1955.27 r0 bottom value=6.2V
D24 "" powerDI123 7024.45,1945 r0 bottom value=6.2V
D25 "" SOT-323 455.5,1762 r0 top value=DESD1P0RFW-7
D26 "DESD1P0RFW-7" SOT-323 1653.49,1762 r180 top value=DNP
D27 "DESD1P0RFW-7" SOT-323 2669.49,1762 r180 top value=DNP
D28 "" SOT-323 637.5,1762 r180 top value=DESD1P0RFW-7
D29 "MBR0520L" SOD-123 863,1100 r0 bottom value=20V
D30 "MBR0520L" SOD-123 1073,1100 r0 bottom value=20V
D31 "DESD1P0RFW-7" SOT-323 1471.5,1762 r0 top value=DNP
D32 "MBR0520L" SOD-123 1884,1100 r0 bottom value=20V
D33 "MBR0520L" SOD-123 2094,1100 r0 bottom value=20V
D34 "DESD1P0RFW-7" SOT-323 2487.5,1762 r0 top value=DNP
D35 "MBR0520L" SOD-123 2855,1111 r0 bottom value=20V
D36 "MBR0520L" SOD-123 3095,1110 r0 bottom value=20V
D37 "MBR0520L" SOD-123 3575.2,1102.09 r0 bottom value=20V
D38 "MBR0520L" SOD-123 3790.2,1099.72 r0 bottom value=20V
D39 "MBR0520L" SOD-123 6834.45,1100 r180 bottom value=20V
D40 "MBR0520L" SOD-123 7059.45,1100 r0 bottom value=20V
FB1 "" FB0603 3840.2,2139.72 r90 top value="1000 OHM"
FB2 "MMZ1608B102C" FB0603 586,2055 r270 top value="1000 OHM"
FB3 "MMZ1608B102C" FB0603 521,2055 r270 top value="1000 OHM"
FB4 "MMZ1608B102C" FB0603 1602,2055 r270 top value="1000 OHM"
FB5 "MMZ1608B102C" FB0603 1537,2055 r270 top value="1000 OHM"
FB6 "MMZ1608B102C" FB0603 6500.45,2055 r270 top value="1000 OHM"
FB7 "MMZ1608B102C" FB0603 2617.99,2055 r270 top value="1000 OHM"
FB8 "" FB0603 2985,2018 r0 bottom value="1000 OHM"
FB9 "" FB0603 948,2010 r0 bottom value="1000 OHM"
FB10 "" FB0603 1969,2010 r0 bottom value="1000 OHM"
FB11 "" FB0603 3492.6,1882.48 r90 bottom value="1000 OHM"
FB12 "" FB0603 443,1770 r90 bottom value="1000 OHM"
FB13 "" FB0603 1459,1770 r90 bottom value="1000 OHM"
FB14 "" FB0603 2479,1780.27 r90 bottom value="1000 OHM"
FB15 "" FB0603 6879.45,1750 r90 bottom value="1000 OHM"
FB16 "MMZ1608B102C" FB0603 6420.45,2055 r270 top value="1000 OHM"
FB17 "MMZ1608B102C" FB0603 2552.99,2050 r270 top value="1000 OHM"
FB18 "MMZ1608B102C" FB0603 4532.38,1443.01 r270 top value="1000 OHM"
FB19 "MMZ1608B102C" FB0603 4442.38,1443.01 r270 top value="1000 OHM"
FB20 "MMZ1608B102C" FB0603 5217.67,1452.27 r270 top value="1000 OHM"
FB21 "MMZ1608B102C" FB0603 5132.67,1452.27 r270 top value="1000 OHM"
FB22 "MMZ1608B102C" FB0603 5886.5,1452.5 r270 top value="1000 OHM"
FB23 "MMZ1608B102C" FB0603 5801.5,1452.5 r270 top value="1000 OHM"
FID1 "" Fiducial10-20 6951,2482 r90 top
FID2 "" Fiducial10-20 196.85,2165.35 r0 top
FID3 "" Fiducial10-20 366,95 r0 top
FID4 "" Fiducial10-20 7177,383 r0 top
FID5 "" Fiducial10-20 6951,2482 r180 bottom
FID6 "" Fiducial10-20 196.85,2165.35 r180 bottom
FID7 "" Fiducial10-20 366,95 r180 bottom
FID8 "" Fiducial10-20 7177,383 r180 bottom
J1 "" HDR100_1X2 957,2340 r270 top value=68001-402HLF
J2 "" HDR100_1X2 837,2340 r270 top value=68001-402HLF
J3 "" HDR100_1X2 1973,2340 r270 top value=68001-402HLF
J4 "" HDR100_1X2 1853,2340 r270 top value=68001-402HLF
J5 "" HDR100_1X2 2988.99,2340 r270 top value=68001-402HLF
J6 "" HDR100_1X2 2868.99,2340 r270 top value=68001-402HLF
J7 "" HDR100_1X2 6751.45,2340 r270 top value=68001-402HLF
J8 "" HDR100_1X2 6871.45,2340 r270 top value=68001-402HLF
J9 "ED120/2DS" CONN_ED120-2DS 546,2401 r90 top
J10 "ED120/2DS" CONN_ED120-2DS 1562,2401 r90 top
J11 "ED120/2DS" CONN_ED120-2DS 2577.99,2401 r90 top
J12 "ED120/2DS" CONN_ED120-2DS 4261,2350 r90 top
J13 "ED120/2DS" CONN_ED120-2DS 4950,2350 r90 top
J14 "ED120/2DS" CONN_ED120-2DS 5697.52,2350 r90 top
J15 "ED120/2DS" CONN_ED120-2DS 6460.45,2350 r90 top
J16 "" HDR100_1X2 3535.2,1544.72 r0 top value=68001-402HLF
J17 "" HDR100_1X2 3825.2,1444.72 r180 top value=68001-402HLF
J18 "" HDR100_1X2 818,1430 r0 top value=68001-402HLF
J19 "" HDR100_1X2 1148,1430 r180 top value=68001-402HLF
J20 "" HDR100_1X2 1829,1425 r0 top value=68001-402HLF
J21 "" HDR100_1X2 2154,1425 r180 top value=68001-402HLF
J22 "" HDR100_1X2 2472.99,1270 r90 top value=68001-402HLF
J23 "" HDR100_1X2 2845,1425 r0 top value=68001-402HLF
J24 "" HDR100_1X2 3175,1420 r180 top value=68001-402HLF
J25 "" HDR100_1X2 6939.45,1420 r180 top value=68001-402HLF
J26 "" HDR100_1X2 441,1270 r90 top value=68001-402HLF
J27 "" HDR100_1X2 1457,1270 r90 top value=68001-402HLF
J28 "" HDR100_1X2 4725.89,1290.01 r90 top value=68001-402HLF
J29 "" HDR100_1X2 5401.19,1290.01 r90 top value=68001-402HLF
J30 "" HDR100_1X2 6067.5,1291.5 r90 top value=68001-402HLF
J31 "" HDR100_1X2 6564.45,1440 r0 top value=68001-402HLF
J32 "2-826634-0" CONN_61304021021 3641.73,206.69 r180 top
LBL1 "" Label_650x200 1255,155 r180 top
Logo1 "Pb-Free Symbol" Pb-Free_Overlay_Small 6287,176 r0 top
LOGO2 "DANGER HIGH VOLTAGE" IEC_HighVoltage_Medium 3296,1900 r0 top
Logo3 "FCC disclaimer" FCC_disclaimer 6290,83.19 r0 top
Logo4 "WEEE logo" WEEE_Minimum 5488.35,320.99 r0 top
Logo5 "ESD Susceptible" ESD_Overlay_small 1760.3,145.65 r0 top
MH1 "" MH3.2 137.8,2421.26 r0 top
MH2 "" MH3.2 7145.67,2421.26 r0 top
MH3 "" MH3.2 137.8,137.8 r0 top locked
MH4 "" MH3.2 7145.67,137.8 r0 top locked
R1 "" 0603 3675.2,2294.72 r270 top value=3.9k
R2 "" 0603 3745.2,2294.72 r270 top value=3.9k
R3 "" 0603 1113,2270 r270 top value=3.9k
R4 "" 0603 2139,2275 r270 top value=3.9k
R5 "" 0603 3095.4,2226.6 r270 top value=3.9k
R6 "CRCW06030000Z0EA" 0603 4297.38,1753.01 r0 top value=0
R7 "CRCW08050000Z0EA" 0805_HV 4301,2000 r270 top value=0
R8 "CRCW08050000Z0EA" 0805_HV 4206,2000 r270 top value=0
R9 "CRCW06030000Z0EA" 0603 4952.69,1743.01 r0 top value=0
R10 "CRCW08050000Z0EA" 0805_HV 5010,2000 r270 top value=0
R11 "CRCW08050000Z0EA" 0805_HV 4900,2000 r270 top value=0
R12 "CRCW06030000Z0EA" 0603 5627.01,1744.51 r0 top value=0
R13 "CRCW08050000Z0EA" 0805_HV 5757.52,2002.5 r270 top value=0
R14 "" 0603 3640.2,1914.72 r0 top value=11.5k
R15 "" 0603 3780.2,1914.72 r0 top value=37.4k
R16 "" 0603 4297.38,1688.01 r0 top value=4.70k
R17 "" 0603 4952.69,1678.01 r0 top value=4.70k
R18 "" 0603 5626.5,1677.5 r0 top value=4.70k
R19 "CRCW08050000Z0EA" 0805_HV 5647.52,2002.5 r270 top value=0
R20 "WSLP39213L000FEB" RC3921 539,2236 r0 bottom value=0.003
R21 "" 0603 4637.38,1486.01 r180 top value=0
R22 "WSLP39213L000FEB" RC3921 1554,2236 r0 bottom value=0.003
R23 "WSLP39213L000FEB" RC3921 2572,2236 r0 bottom value=0.003
R24 "" 0603 5317.67,1482.27 r180 top value=0
R25 "CRCW06030000Z0EA" 0603 6410,538.5 r90 top value=0
R26 "CRCW06030000Z0EA" 0603 6409.5,1196.8 r0 top value=0
R27 "" 0603 5991.5,1487.5 r180 top value=0
R28 "" 0603 436.5,1530 r0 top value=3.9k
R29 "CRCW06030000Z0EA" 0603 6440,1298 r90 top value=0
R30 "" 0603 1452.5,1530 r0 top value=3.9k
R31 "RC0402JR-070RL" 0402M 3451,1354 r270 bottom value=0
R32 "" 0603 2467.99,1529.5 r0 top value=3.9k
R33 "CRCW06030000Z0EA" 0603 4237,460 r180 bottom value=0
R34 "CRCW06030000Z0EA" 0603 4240.42,1379 r180 bottom value=0
R35 "RC0603JR-0747KL" 0603 4533,597 r270 bottom value=47k
R36 "RC0402JR-070RL" 0402M 4436,630 r0 bottom value=0
R38 "CRCW0603100KFKEA" 0603 4201,1265 r270 bottom value=100k
R39 "" 0603 526,542.5 r270 top value=10.0
R40 "RC0603JR-0747KL" 0603 4138,591 r270 bottom value=47k
R41 "ERJ-2RKF1001X" 0402 4208,604.51 r90 bottom value=1.00k
R42 "" 0603 1542,542.5 r270 top value=10.0
R43 "CRCW0603100KFKEA" 0603 4137,1265 r270 bottom value=100k
R44 "RC0402JR-070RL" 0402M 3981,640 r180 bottom value=0
R45 "RC0402JR-070RL" 0402M 4037.44,1216 r0 bottom value=0
R46 "" 0603 2556.99,542.87 r270 top value=10.0
R48 "" 0603 4459.89,545.51 r270 top value=10.0
R51 "" 0603 5135.19,545.51 r270 top value=10.0
R55 "" 0603 5801.5,542.5 r270 top value=10.0
R58 "" 0603 6475,538 r270 top value=10.0
R59 "" 0603 2985.4,1951.6 r180 bottom value=37.4k
R60 "" 0603 6939.45,2025 r180 bottom value=3.9k
R61 "" 0603 948,1940 r180 bottom value=37.4k
R62 "" 0603 1969,1940 r180 bottom value=37.4k
R63 "" 0603 3135.4,1861.6 r180 bottom value=11.5k
R64 "" 0603 1098,1850 r180 bottom value=11.5k
R65 "" 0603 2119,1850 r180 bottom value=11.5k
T1 "750342271" 760390015 908,740 r90 top value=469uH
T2 "750342271" 760390015 1929,740 r90 top value=469uH
T3 "750342271" 760390015 2915,760 r90 top value=469uH
T4 "750342271" 760390015 3525.2,739.72 r90 top value=469uH
T5 "750342271" 760390015 6849.45,740 r90 top value=469uH
TP1 "" TP-040_RND 3562,2389 r0 top value=STD
TP2 "" TP-040_RND 6914.45,1840 r0 top value=STD
TP3 "" TP-040_RND 338,1825 r90 top value=STD
TP4 "" TP-040_RND 1354,1825 r90 top value=STD
TP5 "" TP-040_RND 2369.99,1825 r90 top value=STD
TP6 "" TP-040_RND 659,481.5 r0 top value=STD
TP7 "" TP-040_RND 1675,481.5 r0 top value=STD
TP8 "" TP-040_RND 2689.99,481.87 r0 top value=STD
TP9 "" TP-040_RND 4621,485 r0 top value=STD
TP10 "" TP-040_RND 5268.19,484.51 r90 top value=STD
TP11 "" TP-040_RND 5934.5,481.5 r180 top value=STD
TP12 "" TP-040_RND 6573.45,479 r90 top value=STD
TP13 "Pogo Pad" PogoPad 4048,474 r90 bottom
TP14 "5002" Keystone5002 4719,707 r90 top
TP15 "Pogo Pad" PogoPad 3937,474 r90 bottom
TP16 "5001" Keystone5001 4009,1332 r90 top
U1 "" MSOP8(DGN) 3755.2,1689.72 r270 top
U2 "OPA211ID" SO8 4522.38,1668.01 r0 top
U3 "OPA211ID" SO8 5177.69,1658.01 r0 top locked
U4 "OPA211ID" SO8 5851.5,1657.5 r0 top
U5 "AMC1306M25DWVR" DWV0008A 550,887.43 r270 top
U6 "AMC1306M25DWVR" DWV0008A 1566,887.43 r270 top
U7 "AMC1306M25DWVR" DWV0008A 2581.99,887.43 r270 top
U8 "AMC1336DWVR" DWV0008A 4484.89,890.08 r270 top
U9 "AMC1336DWVR" DWV0008A 5160.19,890.08 r270 top
U10 "AMC1336DWVR" DWV0008A 5826.5,887.07 r270 top
U11 "AMC1311BDWVR" DWV0008A 6465.45,884.57 r270 top
U12 "SN6501DBV" DBV0005A_N 1008,615 r270 top
U13 "SN6501DBV" DBV0005A_N 2029,615 r270 top
U14 "SN6501DBV" DBV0005A_N 3030,625 r270 top
U15 "SN6501DBV" DBV0005A_N 3615.2,614.72 r270 top
U16 "SN6501DBV" DBV0005A_N 6949.45,615 r270 top
U17 "" MSOP8(DGN) 3001.2,1736.6 r270 bottom
U18 "TLV70450DBV" DBV0005A_N 3637.6,1782.48 r90 bottom
U19 "TPS7A3001DGNR" MSOP8(DGN) 963,1725 r270 bottom
U20 "" MSOP8(DGN) 1984,1725 r270 bottom
U21 "TLV70450DBV" DBV0005A_N 578,1645 r90 bottom
U22 "TLV70450DBV" DBV0005A_N 1594,1644.5 r90 bottom
U23 "TLV70450DBV" DBV0005A_N 2614,1655.27 r90 bottom
U24 "TLV76050DBZR" DBZ0003A_N 7066.85,1645 r90 bottom
U25 "UCC12050DVER" DVE0016A 4198,924 r90 bottom
ZZ1 "This Assembly Note is for PCB labels only" AssemblyNoteLabel 181,3347 r0 top
ZZ2 "These assemblies are ESD sensitive, ESD precautions shall be observed." AssemblyNote 181,3238.11 r0 top
ZZ3 "These assemblies must be clean and free from flux and all contaminants. Use of no clean flux is not acceptable." AssemblyNote 181,3149.56 r0 top
ZZ4 "These assemblies must comply with workmanship standards IPC-A-610 Class 2, unless otherwise specified." AssemblyNote 181,3061 r0 top

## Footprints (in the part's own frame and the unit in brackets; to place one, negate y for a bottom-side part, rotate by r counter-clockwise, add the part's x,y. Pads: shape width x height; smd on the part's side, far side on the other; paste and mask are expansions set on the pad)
0402 [mm] "0402 from SM-752 data"
  rect 0.8x0.6 smd: 1(-0.6,0) 2(0.6,0)
  silkscreen extent -1.22,-0.52 1.22,0.52, body extent -0.55,-0.3 0.55,0.3, height 0.6
0402M [mm] "0402 from SM-752 data"
  rect 1x0.7 smd: 1(-0.7,0) 2(0.7,0)
  silkscreen extent -1.5,-0.64 1.51,0.65, body extent -0.55,-0.3 0.55,0.3, height 0.6
0603 [mm] "0603 from SM-752 data"
  rect 1x0.95 smd: 1(-0.8,0) 2(0.8,0)
  silkscreen extent -1.52,-0.69 1.52,0.69, body extent -0.87,-0.47 0.87,0.47, height 0.85
0805_HV [mil] "0805 with 30mil clearance between pads"
  rect 50x63 smd: 1(-40,0) 2(40,0)
  silkscreen extent -74,-40 74,40, body extent -43,-29 43,29, height 43
1206_180 [mm] "1206_180"
  rect 1.1x1.6 smd: 1(-1.7,0) 2(1.7,0)
  silkscreen extent -0.9,-1 0.9,1, body extent -1.75,-0.95 1.75,0.95, height 1.8
1210 [mm] "1210 from SM-752 data"
  rect 1.3x2.7 smd: 1(-1.45,0) 2(1.45,0)
  silkscreen extent -2.32,-1.57 2.32,1.57, body extent -1.7,-1.35 1.7,1.35, height 1.35
760390015 [mm]
  rect 1.27x0.66 smd: 1(0,0) 2(0,-2.54) 3(0,-5.08) 4(9.14,-5.08) 5(9.14,-2.54) 6(9.14,0)
  silkscreen extent -1.72,-6.35 10.2,1.27, body extent -1,-6.4 10.2,1.2, height 4.2
AssemblyNote [mil] "Assembly Note"
AssemblyNoteLabel [mil] "Assembly Note for PCB Labels"
CAP_200mil#1 [mil]
  round 60 hole 32 mask+5: 1(-100,0) 2(100,0)
  silkscreen extent -205,-80 205,80
CAP_200mil#2 [mil]
  round 60 hole 32 mask+5: 1(-100,0)
  round 60 hole 32 mask+4: 2(100,0)
  silkscreen extent -205,-80 205,80
CONN_61304021021 [mil]
  rect 60x60 hole 38: 1(952,50)
  round 60 hole 38: 2(952,-50) 3(852,50) 4(852,-50) 5(752,50) 6(752,-50) 7(652,50) 8(652,-50) 9(552,50) 10(552,-50) 11(452,50) 12(452,-50) 13(352,50) 14(352,-50) 15(252,50) 16(252,-50) 17(152,50) 18(152,-50) 19(52,50) 20(52,-50) 21(-48,50) 22(-48,-50) 23(-148,50) 24(-148,-50) 25(-248,50) 26(-248,-50) 27(-348,50) 28(-348,-50) 29(-448,50) 30(-448,-50) 31(-548,50) 32(-548,-50) 33(-648,50) 34(-648,-50) 35(-748,50) 36(-748,-50) 37(-848,50) 38(-848,-50) 39(-948,50) 40(-948,-50)
CONN_ED120-2DS [mm] "ONSHORE"
  rect 1.75x1.75 hole 1.25: 1(0,-2.54)
  round 1.75 hole 1.25: 2(0,2.54)
  silkscreen extent -5,-5.6 4,5.12, body extent -5,-5.6 4.15,5.12, height 13.1
DBV0005A_N [mm] "SOT23, 5-Leads, Body 2.9x1.6mm, Pitch 0.95mm, Lead Span 2.8mm, IPC Medium Density"
  rect 1.1x0.65 smd: 1(-1.2,0.95) 2(-1.2,0) 3(-1.2,-0.95) 4(1.2,-0.95) 5(1.2,0.95)
  silkscreen extent -1.9,-1.55 0.25,1.78, body extent -1.42,-1.46 1.42,1.46, height 1.08
DBZ0003A_N [mm] "SOT23, 3-Leads, Body 2.9x1.3mm, Pitch 0.95mm, Lead Span 2.4mm, IPC Medium Density"
  rrect17% 1x0.6 smd: 1(-1.2,0.95) 2(-1.2,-0.95) 3(1.2,0)
  silkscreen extent 0.2,-1.5 0.7,1.5, body extent -1.26,-1.46 1.26,1.46, height 0.98
DVE0016A [mm] "SO-MOD-16"
  rrect17% 1.65x0.6 smd: 1(-4.875,4.445) 2(-4.875,3.175) 3(-4.875,1.905) 4(-4.875,0.635) 5(-4.875,-0.635) 6(-4.875,-1.905) 7(-4.875,-3.175) 8(-4.875,-4.445) 9(4.875,-4.445) 10(4.875,-3.175) 11(4.875,-1.905) 12(4.875,-0.635) 13(4.875,0.635) 14(4.875,1.905) 15(4.875,3.175) 16(4.875,4.445)
  body extent -5.17,-5.15 5.17,5.15, height 2.59
DWV0008A [mm] "SOIC, 8-Leads, Body 5.95x7.6mm (max), Pitch 1.27mm"
  rrect17% 1.8x0.6 smd: 1(-5.45,1.905) 2(-5.45,0.635) 3(-5.45,-0.635) 4(-5.45,-1.905) 5(5.45,-1.905) 6(5.45,-0.635) 7(5.45,0.635) 8(5.45,1.905)
  silkscreen extent -6.25,-2.95 2.98,2.95, body extent -5.77,-2.92 5.77,2.93, height 2.67
ESD_Overlay_small [mil]
  silkscreen extent -62,-48 64,61
FB0603 [mm]
  rect 0.95x1 smd: 1(-0.75,0) 2(0.75,0)
  silkscreen extent -0.8,-0.7 0.8,0.7
FCC_disclaimer [mil]
Fiducial10-20 [mm]
  round 1 smd paste+0 mask+0.5: 1(0,0)
  Top Layer keep-out circle w1.178: c0,0 r0.5
HDR100_1X2 [mil]
  rect 60x60 hole 38: 1(0,0)
  round 60 hole 38: 2(100,0)
  silkscreen extent -82,-50 150,50
IEC_HighVoltage_Medium [mil]
  silkscreen extent -217,-176 217,200
Keystone5001 [mil] "For Keystone 500x miniature loop terminals"
  round 80 hole 40: 1(0,0)
  silkscreen extent -52,-52 52,52, body extent -49,-49 49,49, height 182
Keystone5002 [mil] "For Keystone 500x miniature loop terminals"
  round 80 hole 40: 1(0,0)
  silkscreen extent -52,-52 52,52, body extent -49,-49 49,49, height 182
Label_650x200 [mil] "Thermal Transfer Label"
  round 1 on Mech13: 0(0,0)
  silkscreen extent -325,-100 325,100, body extent -325,-100 325,100, height 1
LED0603AA [mil]
  rect 32x32 smd: 1(-32.48,0) 2(32.48,0)
  silkscreen extent -132,-25 11,25
MH3.2 [mil]
  round 128 / inner round 142 / far side round 128 hole 128 unplated mask+10: 1(0,0)
  silkscreen extent -120,-120 120,120
MSOP8(DGN) [mil]
  rect 50x15 smd mask+3: 1(-77,38) 2(-77,12.4) 3(-77,-13.2) 4(-77,-38.8) 5(76.6,-38.8) 6(76.6,-13.2) 7(76.6,12.4) 8(76.6,38)
  rect 60x75 smd: 9(0,-0.8)
  silkscreen extent -108,80 -83,105
Pb-Free_Overlay_Small [mil]
  silkscreen extent -46,-46 46,46
PogoPad [mil] "No Solder Paste"
  round 70 smd paste-35: 1(0,0)
powerDI123 [mm] "Diodes Inc recommended land pattern, document number DS30628 Rev. 6-2"
  rect 2.2x1.4 smd: 1(-1.275,0)
  rect 0.9x1.4 smd: 2(1.275,0)
  silkscreen extent -3.1,-1.09 1.76,1.09, body extent -2.38,-0.97 1.52,0.96, height 1
RC3921 [mm] "RESISTOR, SMD, 3921"
  rect 2.7x5.45 smd mask+0.102: 1(-4.15,0) 2(4.15,0)
  silkscreen extent -2.45,-2.6 2.45,2.6, body extent -5,-2.6 5,2.6, height 0.93
SM_RADIAL_5MM [mm] "Nichicon 5x5.8"
  rect 3x1.6 smd: 1(-2.2,0) 2(2.2,0)
  silkscreen extent -3.81,-2.75 2.75,2.75, body extent -2.75,-2.75 2.75,2.75, height 6.1
SO8 [mil]
  rect 80x26 smd: 1(-95,75) 2(-95,25) 3(-95,-25) 4(-95,-75) 5(94,-75) 6(94,-25) 7(94,25) 8(94,75)
  silkscreen extent -135,115 -95,155
SOD-123 [mm] "On Semi recommended land pattern"
  rect 0.915x1.22 smd: 1(-1.637,0) 2(1.637,0)
  silkscreen extent -2.74,-1.17 2.03,1.17, body extent -1.93,-0.9 1.93,0.9, height 1.35
SOT-323 [mm] "Zetex recommended land pattern.  March 2007"
  rect 0.8x0.6 smd: 1(-0.8,0.65) 2(-0.8,-0.65) 3(0.8,0)
  silkscreen extent -1.14,-1.22 1.09,1.49, body extent -1.13,-1.13 1.12,1.12, height 1.13
TP-040_RND [mil]
  round 70 / inner round 62 / far side round 62 hole 40: 1(0,0)
  silkscreen extent -45,-45 45,45
WEEE_Minimum [mil] "WEEElie bin"
  silkscreen extent -95,-172 99,104

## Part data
C1 C85 C90 C92 C95 C102 C103 C104 C106: library part C2012X5R1H475K125AB, "CAP, CERM, 4.7uF, 50V, +/-10%, X5R, 0805", Cap_Case=0805, Manufacturer=TDK, Supplier Part Number 1=445-5980-1-ND, TempCo=X5R, Tolerance_%=10, Value1=Unknown, Value2=50V, ValueDisplayed=4.7µF
C2 C20 C22 C24 C26 C29 C30 C31 C32 C33 C34 C35 C36 C39 C42 C45 C46 C47 C48 C50 C52 C54 C56 C69 C71 C73 C75 C77 C86 C87 C89 C93 C96 C98 C100 C101 C105 C112 C114 C115 C118 C119 C122 C124 C127 C128 C130 C132 C133 C134 C135 C137: library part C0603C104K5RACTU, "CAP, CERM, 0.1uF, 50V, +/-10%, X7R, 0603", Cap_Case=0603, Manufacturer=Kemet, Supplier Part Number 1=399-5089-1-ND, TempCo=X7R, Tolerance_%=10, Value1=Unknown, Value2=50V, ValueDisplayed=0.1µF
C3 C4 C5 C6 C7 C8 C10 C11 C37 C38 C40 C41 C43 C44: "CAP, CERM, 47pF, 500V, +/-5%, C0G/NP0, 0805", Cap_Case=0805, Manufacturer=MuRata, Supplier Part Number 1=490-5538-1-ND, TempCo=C0G/NP0, Tolerance_%=5, Value1=Unknown, Value2=250V, ValueDisplayed=47pF
C9 C17 C18 C19 C28 C49 C70 C72 C74 C76 C78 C84 C88 C91 C107 C108 C109 C111 C113 C117 C121 C123 C125 C126 C129 C131 C136 C138 C139 C140 C141 C142 C143 C144 C145 C146 C147 C148 C149: library part GMK325AB7106MM-T, "CAP, CERM, 10uF, 35V, +/-20%, X7R, 1210", Cap_Case=1210, Manufacturer="Taiyo Yuden", Supplier Part Number 1=587-2779-1-ND, TempCo=X7R, Tolerance_%=20, Value1=Unknown, Value2=35V, ValueDisplayed=10µF
C12 C13 C14 C16 C51 C53 C55: "CAP, CERM, 1500pF, 100V, +/-10%, X7R, 0603", Cap_Case=0603, Manufacturer=AVX, Supplier Part Number 1=478-1200-1-ND, TempCo=X7R, Tolerance_%=10, Value1="0.229 ohm", Value2=100V, ValueDisplayed=1500pF
C15 C27 C94 C97 C99 C110 C116 C120: library part 06031C103JAT2A, "CAP, CERM, 0.01uF, 100V, +/-5%, X7R, 0603", Cap_Case=0603, Manufacturer=AVX, PartNumber=06031C103J4Z4A, Supplier Part Number 1=478-7418-1-ND, TempCo=X7R, Tolerance_%=5, Value1="0.098 ohm", Value2=100V, ValueDisplayed=0.01µF
C21 C23 C25: library part 06031C472KAT2A, "CAP, CERM, 4700pF, 100V, +/-10%, X7R, 0603", Cap_Case=0603, Manufacturer=AVX, Supplier Part Number 1=478-1203-1-ND, TempCo=X7R, Tolerance_%=10, Value1="0.136 ohm", Value2=100V, ValueDisplayed=4700pF
C57 C58 C59 C60: library part 202R18W102KV4E, "CAP CER 1000PF 1KV 10% RADIAL", Manufacturer="Vishay BC Components", PartNumber=S102K29Y5PN63J5R, Supplier Part Number 1=1251PH-ND, Tolerance_%=0, Value2=1kv, ValueDisplayed=1000pF
C61 C62 C63 C64 C65 C66 C67: library part 06033C104JAT2A, "CAP, CERM, 0.1uF, 25V, +/-5%, X7R, 0603", Cap_Case=0603, Manufacturer=AVX, Supplier Part Number 1=478-3713-1-ND, TempCo=X7R, Tolerance_%=5, Value1="0.05 ohm", Value2=25V, ValueDisplayed=0.1µF
C68 C79 C80 C81 C82 C83: "CAP, AL, 22uF, 25V, +/-20%, 0.76 ohm, SMD", Cap_Case=5x5.8, Manufacturer=Nichicon, Supplier Part Number 1=493-2270-1-ND, Tolerance_%=20, Value1="0.76 ohm", Value2=25V, ValueDisplayed=22µF
C150 C152: "CAP, CERM, 0.1uF, 50V, +/-10%, X7R, 0603", Cap_Case=0603, Manufacturer=Kemet, Supplier Part Number 1=399-5089-1-ND, TempCo=X7R, Tolerance_%=10, Value1=Unknown, Value2=50V, ValueDisplayed=0.1µF
C154 C155: "CAP, CERM, 10 µF, 50 V, +/- 10%, X5R, 1206", Cap_Case=1206, Manufacturer=MuRata, Supplier Part Number 1=490-5961-1-ND, TempCo=X5R, Tolerance_%=10, Value1=Unknown, Value2=50V, ValueDisplayed=10µF
D1 D2 D3 D4 D5 D7 D14 D15 D16: library part "LED_LG L29K-G2J1-24-Z", "LED SmartLED Green 570NM", Alternate Manufacturer=LED, Manufacturer=OSRAM, PartNumber="LG L29K-G2J1-24-Z", Supplier Part Number 1=475-2709-2-ND
D6 D17 D18 D19 D20 D21 D22 D23 D24: library part DFLZ6V2-7, "Diode, Zener, 6.2V, 1W, PowerDI123", Manufacturer="Diodes Inc.", Power_W=1, Supplier Part Number 1=DFLZ6V2DICT-ND, Value1=1W
D8 D9 D10 D26 D27 D31 D34: library part BAV99WT1G, "Diode, P-N, 70V, 0.2A, SOT-323", Manufacturer="Diodes Inc", Supplier Part Number 1=DESD1P0RFW-7DIDKR-ND
D11 D12 D13 D25 D28: library part BAV99WT1G, "Diode, P-N, 70V, 0.2A, SOT-323", Manufacturer="Diodes Inc", PartNumber=DESD1P0RFW-7, Supplier Part Number 1=DESD1P0RFW-7DIDKR-ND
D29 D30 D32 D33 D35 D36 D37 D38 D39 D40: library part MBR0520LT1G, "Diode, Schottky, 20V, 0.5A, SOD-123", Manufacturer="Fairchild Semiconductor", Supplier Part Number 1=MBR0520LCT-ND, Value1=0.5A, Value2=0.385V
FB1 FB8 FB9 FB10 FB11 FB12 FB13 FB14 FB15: library part MMZ1608B102C, "FERRITE CHIP 1000 OHM 300MA 0603", Manufacturer="TDK Corporation", Supplier Part Number 1=445-8672-1-ND
FB2 FB3 FB4 FB5 FB6 FB7 FB16 FB17 FB18 FB19 FB20 FB21 FB22 FB23: "FERRITE CHIP 1000 OHM 300MA 0603", Manufacturer="TDK Corporation", Supplier Part Number 1=445-8672-1-ND
FID1 FID2 FID3 FID4 FID5 FID6 FID7 FID8: library part Fiducial, "Fiducial mark.  There is nothing to buy or mount.", Manufacturer=N/A
J1 J2 J3 J4 J5 J6 J7 J8 J16 J17 J18 J19 J20 J21 J22 J23 J24 J25 J26 J27 J28 J29 J30 J31: library part JUMPER_2X100MIL, "Header, Male 2-pin, 100mil spacing,", Manufacturer=FCI, PartNumber=68001-402HLF, Supplier Part Number 1=609-3507-ND
J9 J10 J11 J12 J13 J14 J15: "TERMINAL BLOCK 5.08MM VERT 2POS, TH", Manufacturer="On-Shore Technology", Supplier Part Number 1=ED1609-ND
J32: library part CONN_61304021021, "Connector, Right Angle 2x20 pin, 100mil spacing", Manufacturer="TE Connectivity", Supplier Part Number 1=A106438-ND
LBL1: library part THT-14-423-10, "Thermal Transfer Printable Labels, 0.650\" W x 0.200\" H - 10,000 per roll", Alternate Manufacturer=-, Manufacturer=Brady, Supplier Part Number 1=2065596
Logo1: library part Pb-Free
LOGO2: library part IEC_HighVoltage, "IEC 61010-1 High Voltage Warning"
Logo3: library part FCC_disclaimer, "FCC_disclaimer"
Logo4: library part CMP-0074769-1
Logo5: library part ESD_Susceptible, "ESD Susceptible Symbol"
MH1 MH2 MH3 MH4: library part "NY PMS 440 0025 PH", "Mountin hole, NPTH Drill 3.2mm", Alternate Manufacturer=-
R1 R2 R3 R4 R5 R28 R30 R32 R60: library part CRCW06033K90JNEA, "RES, 3.9k ohm, 5%, 0.1W, 0603", Manufacturer=Vishay-Dale, Power_W=0.1, Supplier Part Number 1=541-3.9KGCT-ND, TempCo="200 ppm/C", Tolerance_%=5, Value1=5%, Value2=0.1W, Value_Code=3k90
R6 R9 R12: "RES, 0 ohm, 5%, 0.1W, 0603", Manufacturer=Vishay-Dale, Power_W=0.1, Supplier Part Number 1=541-0.0GCT-ND, TempCo="200 ppm/C", Tolerance_%=5, Value1=5%, Value2=0.1W, Value_Code=0000
R7 R8 R10 R11 R13 R19: "RES, 0 ohm, 5%, 0.125W, 0805", Manufacturer=Vishay-Dale, Power_W=0.125, Supplier Part Number 1=541-0.0ACT-ND, TempCo="200 ppm/C", Tolerance_%=5, Value1=5%, Value2=0.125W, Value_Code=0000
R14 R63 R64 R65: library part CRCW060311K5FKEA, "RES, 11.5k ohm, 1%, 0.1W, 0603", Manufacturer=Vishay-Dale, Power_W=0.1, Supplier Part Number 1=541-11.5KHCT-ND, TempCo="100 ppm/C", Tolerance_%=1, Value1=1%, Value2=0.1W, Value_Code=11k5
R15 R59: library part RT0603BRD0737KL, "RES 37.4K OHM 1/10W .1% 0603 SMD", Manufacturer=Panasonic, PartNumber=ERA-3AEB3742V, Power_W=0.1, Supplier Part Number 1=P37.4KDBCT-ND, TempCo="25 ppm/C", Value1=1%, Value2=0.1W, Value_Code=37k4
R16 R17 R18: library part RC0603FR-074K7L, "RES, 4.70k ohm, 1%, 0.1W, 0603", Manufacturer="Yageo America", Power_W=0.1, Supplier Part Number 1=311-4.70KHRCT-ND, TempCo="200 ppm/C", Tolerance_%=1, Value1=1%, Value2=0.1W, Value_Code=4k70
R20 R22 R23: "RESISTOR, SMD, 0.003 OHM, 1%, 5W, 3921", Manufacturer="VISHAY DALE"
R21 R24 R27: library part CRCW06030000Z0EA, "RES, 0 ohm, 5%, 0.1W, 0603", Manufacturer=Vishay-Dale, Power_W=0.1, Supplier Part Number 1=541-0.0GCT-ND, TempCo="200 ppm/C", Tolerance_%=5, Value1=5%, Value2=0.1W, Value_Code=0000
R25 R26 R29 R33 R34: "RES, 0, 5%, 0.1 W, 0603", Manufacturer=Vishay-Dale, Power_W=0.1, Supplier Part Number 1=541-0.0GCT-ND, TempCo="200 ppm/C", Tolerance_%=5, Value1=5%, Value2=0.1W, Value_Code=0000, ValueDisplayed=0
R31 R36 R44 R45: "RES, 0 ohm, 5%, 0.063W, 0402", Manufacturer="Yageo America", Power_W=0.063, Supplier Part Number 1=311-0.0JRCT-ND, TempCo="200 ppm/C", Tolerance_%=5, Value1=5%, Value2=0.063W, Value_Code=0000
R35 R40: "RES, 47 k, 5%, 0.1 W, 0603", Manufacturer="Yageo America", Power_W=0.1, Supplier Part Number 1=311-47KGRCT-ND, TempCo="100 ppm/C", Tolerance_%=5, Value1=5%, Value2=0.1W, Value_Code=47k0, ValueDisplayed=47k
R38 R43: "RES, 100 k, 1%, 0.1 W, 0603", Manufacturer=Vishay-Dale, Power_W=0.1, Supplier Part Number 1=541-100KHCT-ND, TempCo="100 ppm/C", Tolerance_%=1, Value1=1%, Value2=0.1W, Value_Code=100k
R39 R42 R46 R48 R51 R55 R58: library part CRCW060310R0FKEA, "RES, 10.0 ohm, 1%, 0.1W, 0603", Manufacturer=Vishay-Dale, Power_W=0.1, Supplier Part Number 1=541-10.0HCT-ND, TempCo="100 ppm/C", Tolerance_%=1, Value1=1%, Value2=0.1W, Value_Code=10R0
R41: "RES, 1.00 k, 1%, 0.1 W, 0402", Manufacturer=Panasonic, Power_W=0.1, Supplier Part Number 1=P1.00KLCT-ND, TempCo="100 ppm/C", Tolerance_%=1, Value1=1%, Value2=0.1W, Value_Code=1k00, ValueDisplayed=1.00k
R61 R62: library part RT0603BRD0737KL, "RES 37.4K OHM 1/10W .1% 0603 SMD", Manufacturer=Panasonic, PartNumber=ERA-3AEB3742V, Power_W=0.1, Supplier Part Number 1=P37.4KDBCT-ND, TempCo="25 ppm/C", Tolerance_%=1%, Value2=0.1W, Value_Code=37k4
T1 T2 T3 T4 T5: library part TRNSFMR, "Transformer 469uH SMD", Manufacturer="Wurth Electronics Midcom"
TP1 TP2 TP3 TP4 TP5 TP6 TP7 TP8 TP9 TP10 TP11 TP12: library part TP-040_RND, "Test Point, O.040 Hole", Manufacturer=STD
TP13 TP15: library part PogoPad, "Pad for Pogo Pin Connector"
TP14: "Test Point, Miniature, White, TH", Color=White, Manufacturer=Keystone, Supplier Part Number 1=36-5002-ND
TP16: "Test Point, Miniature, Black, TH", Color=Black, Manufacturer=Keystone, Supplier Part Number 1=36-5001-ND
U1 U17 U20: library part TPS7A3001DGNR, "-36V, -200mA, Ultralow-Noise, Negative Linear Regulator", Alternate Manufacturer=None, Manufacturer="Texas Instruments"
U2 U3 U4: library part OPA211AID, "IC, 1.1nV/vHz Noise, Low Power, Precision OpAmp", Alternate Manufacturer=None, Manufacturer="Texas Instruments"
U5 U6 U7: "Small Reinforced Isolated Modulator With +/-250mV Input and CMOS Interface, DWV0008A (SOIC-8)", Alternate Manufacturer="Texas Instruments", Alternate PartNumber=AMC1306M25DWV
U8 U9 U10: library part CMP-0860008-1, "AMC1336 Small, High-Precision, Reinforced Isolated Delta-Sigma Modulator With Input Optimized for Voltage Sensing Applications, DWV0008A (SOIC-8)", Alternate Manufacturer="Texas Instruments", Alternate PartNumber=AMC1336DWV
U11: library part AMC1311DWVR, "Precision, 2-V Input, Reinforced Isolated Amplifier, DWV0008A (SOIC-8)", Alternate Manufacturer="Texas Instruments", Alternate PartNumber=AMC1311DWV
